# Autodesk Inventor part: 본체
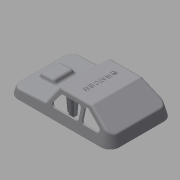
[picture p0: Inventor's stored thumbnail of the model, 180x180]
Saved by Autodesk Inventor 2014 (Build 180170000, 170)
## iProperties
Created: 2015-06
Part Number: 본체
Material: Generic
Document SubType Name: Modeling
Designer: Administrator
Density: 1 g/cm^3
Appearance: Default
Author: Administrator
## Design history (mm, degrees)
sketch "스케치2"
  geometry: L1 (-49, 38)-(49, 38); L2 (61, 26)-(61, -26); L3 (49, -38)-(-49, -38); L4 (-61, -26)-(-61, 26); L5 (-61, 38)-(61, -38); L6 (61, 38)-(-61, -38); A1 r 12 centre (-49, -26) between (-61, -26) and (-49, -38); A2 r 12 centre (-49, 26) between (-49, 38) and (-61, 26); A3 r 12 centre (49, 26) between (61, 26) and (49, 38); A4 r 12 centre (49, -26) between (49, -38) and (61, -26); 1 further point
  constraints: 12 end point, 8 point on circle, 8 point on line, 8 tangent, 4 centre point, 3 equal radius, 2 midpoint, 2 parallel, 1 horizontal, 1 perpendicular
  dimensions: "d0" = 122 distance of L5.end L6.end; "d1" = 76 distance of L6.start L5.end; "d2" = 12 radius of A1
extrude "돌출1" new body sketch "스케치2" distance "d3" = 30; taper "d4" = -15 deg
sketch "스케치3"
  geometry: L1 (-31, 30)-(-61, 30); L2 (-61, 30)-(-61, 10); L3 (-61, 10)-(-31, 30); L4 (49, 30)-(-49, 30) reference; 2 further points
  constraints: 6 end point, 1 collinear, 1 horizontal, 1 perpendicular, 1 vertical alignment
  dimensions: "d5" = 30 distance of L1.start L1.end; "d6" = 20 distance of L1.end L2.end
extrude "돌출2" cut sketch "스케치3" stored distance "d7" = 30; taper "d8" = 0 deg
sketch "스케치4"
  geometry: L1 (1.279, 39.573)-(19, 11.213); L2 (19, 11.213)-(69.975, 8.542); L3 (69.975, 8.542)-(59.484, 45.933); L4 (59.484, 45.933)-(1.279, 39.573); L5 (-49, 0)-(49, 0) reference; L6 (61, 0)-(52.962, 30) reference; 1 further point
  constraints: 8 end point, 1 point on line
  dimensions: "d9" = 3 deg angle of L5 L2; "d10" = 42 horizontal distance of L1.end L6.start; "d11" = 125 deg angle of L1 L2; "d12" = 9 distance from line of L6.start L2
extrude "돌출3" cut sketch "스케치4" stored distance "d13" = 30; taper "d14" = 0 deg
sketch "스케치5"
  geometry: L1 (-31.529, 47.995)-(-11.529, 47.995); L2 (-11.529, 47.995)-(-11.529, 21.995); L3 (-11.529, 21.995)-(-31.529, 21.995); L4 (-31.529, 21.995)-(-31.529, 47.995); L5 (-31.529, 47.995)-(-11.529, 21.995); L6 (-11.529, 47.995)-(-31.529, 21.995); L7 (-30.546, -3.005)-(67.32, -3.005) reference; L8 (-42.529, 60.995)-(-42.529, 8.995) reference; 2 further points
  constraints: 12 end point, 2 midpoint, 2 parallel, 1 horizontal, 1 perpendicular
  dimensions: "d15" = 20 distance of L2.end L3.end; "d16" = 26 distance of L1.end L2.end; "d17" = 38 distance from line of L7 point (-21.529, 34.995); "d18" = 21 distance from line of point (-21.529, 34.995) L8
extrude "돌출4" join sketch "스케치5" distance "d19" = 5; taper "d20" = -20 deg
fillet "모깎기1" dims "d21" = 3
fillet "모깎기2" dims "d22" = 3
fillet "모깎기3" dims "d23" = 3
feature "쉘1" dims "d24" = 2
sketch "스케치6"
  geometry: L1 (-49, 35.929)-(49, 35.929) reference; L2 (58.929, 26)-(58.929, -26) reference; L3 (49, -35.929)-(-49, -35.929) reference; L4 (-58.929, -26)-(-58.929, 26) reference; L5 (49, -38)-(-49, -38) reference; L6 (61, 26)-(61, -26) reference; L7 (-49, 38)-(49, 38) reference; L8 (-61, -26)-(-61, 26) reference; L9 (60, 26)-(60, -26); L10 (49, -37)-(-49, -37); L11 (-60, -26)-(-60, 26); L12 (-49, 37)-(49, 37); A1 r 9.929 centre (-49, 26) between (-49, 35.929) and (-58.929, 26) reference; A2 r 9.929 centre (49, 26) between (58.929, 26) and (49, 35.929) reference; A3 r 9.929 centre (49, -26) between (49, -35.929) and (58.929, -26) reference; A4 r 9.929 centre (-49, -26) between (-58.929, -26) and (-49, -35.929) reference; A5 r 12 centre (49, -26) between (49, -38) and (61, -26) reference; A6 r 12 centre (49, 26) between (61, 26) and (49, 38) reference; A7 r 12 centre (-49, 26) between (-49, 38) and (-61, 26) reference; A8 r 12 centre (-49, -26) between (-61, -26) and (-49, -38) reference; A9 r 11 centre (49, 26) between (60, 26) and (49, 37); A10 r 11 centre (49, -26) between (49, -37) and (60, -26); A11 r 11 centre (-49, -26) between (-60, -26) and (-49, -37); A12 r 11 centre (-49, 26) between (-49, 37) and (-60, 26); 1 further point
  constraints: 8 end point, 8 point on circle, 4 centre point, 7 other
  dimensions: "d25" = 1 distance between parallel lines of L7 L12
extrude "돌출5" join sketch "스케치6" distance "d26" = 1; taper "d27" = 0 deg
sketch "스케치7"
  geometry: L1 (18.172, 12.538)-(8.142, 28.59) reference; L2 (5.598, 30)-(-30.092, 30) reference; L3 (-31.756, 29.496)-(-50.664, 16.891) reference; L4 (10.994, 14.59)-(5.371, 23.59); L5 (2.826, 25)-(-17.138, 25); L6 (8.45, 10)-(-17.138, 10); L7 (-20.138, 22)-(-20.138, 13); L8 (-28.65, 25.557)-(-43.742, 15.496); L9 (-23.986, 23.061)-(-23.986, 13); L10 (-26.986, 10)-(-42.078, 10); A1 r 3 centre (-26.986, 23.061) between (-23.986, 23.061) and (-28.65, 25.557); A2 r 3 centre (-42.078, 13) between (-43.742, 15.496) and (-42.078, 10); A3 r 3 centre (-26.986, 13) between (-26.986, 10) and (-23.986, 13); A4 r 3 centre (-17.138, 22) between (-17.138, 25) and (-20.138, 22); A5 r 3 centre (2.826, 22) between (5.371, 23.59) and (2.826, 25); A6 r 3 centre (8.45, 13) between (8.45, 10) and (10.994, 14.59); A7 r 3 centre (-17.138, 13) between (-20.138, 13) and (-17.138, 10); 5 further points
  constraints: 14 end point, 14 point on circle, 14 tangent, 8 point on line, 7 centre point, 6 equal radius, 5 parallel, 2 perpendicular, 1 collinear
  dimensions: "d34" = 5 distance between parallel lines of L1 L4; "d35" = 5 distance between parallel lines of L2 L5; "d36" = 34 distance from line of L7 point (13.862, 10); "d37" = 15 distance of point (-20.138, 25) point (-20.138, 10); "d38" = 5 distance between parallel lines of L3 L8; "d41" = 28 distance from line of point (-51.986, 10) L9; "d42" = 3 radius of A1
extrude "돌출6" cut sketch "스케치7" stored distance "d43" = 1; taper "d44" = 0 deg
node "작업 평면1"
sketch "스케치8"
  geometry: A1 r 4 centre (-21, 0) between (-17, 0) and (-25, 0); A2 r 4 centre (-10, 0) between (-6, 0) and (-14, 0); A3 r 4 centre (10, 0) between (14, 0) and (6, 0); A4 r 4 centre (21, 0) between (25, 0) and (17, 0); 3 further points
  constraints: 8 point on circle, 4 centre point, 13 other
  dimensions: "d46" = 8 diameter of A1; "d47" = 8 diameter of A2; "d48" = 8 diameter of A3; "d49" = 8 diameter of A4; "d50" = 20 distance of A3.centre A2.centre; "d51" = 10 distance of point (0, 0) A2.centre; "d52" = 11 distance of A2.centre A1.centre; "d53" = 11 distance of A4.centre A3.centre
extrude "돌출7" join sketch "스케치8" stored distance "d54" = 1; taper "d55" = 0 deg
chamfer "모따기1" distance "d56" = 1; stored, may be unused: second distance "d57" = 2, angle "d58" = 45 deg
sketch "스케치9"
  geometry: C1 r 3 at (-40, 0); C2 r 3 at (0, 22); C3 r 3 at (40, 0); C4 r 3 at (0, -22); 1 further point
  constraints: 4 centre point, 2 horizontal alignment, 2 vertical alignment
  dimensions: "d59" = 6 diameter of C1; "d60" = 6 diameter of C2; "d61" = 6 diameter of C3; "d62" = 6 diameter of C4; "d63" = 40 distance of point (0, 0) C1.centre; "d64" = 40 distance of C3.centre point (0, 0); "d65" = 22 distance of C2.centre point (0, 0); "d66" = 44 distance of C2.centre C4.centre
extrude "돌출8" join sketch "스케치9" stored distance "d67" = 1; taper "d68" = 2 deg
sketch "스케치10"
  geometry: 1 further point
node "작업 평면2"
sketch "스케치12"
  geometry: L1 (-5, 23)-(5, 23); L2 (5, 23)-(5, 21); L3 (5, 21)-(-5, 21); L4 (-5, 21)-(-5, 23); L5 (-5, 23)-(5, 21); L6 (5, 23)-(-5, 21); L7 (35, 1)-(45, 1); L8 (45, 1)-(45, -1); L9 (45, -1)-(35, -1); L10 (35, -1)-(35, 1); L11 (35, 1)-(45, -1); L12 (45, 1)-(35, -1); L13 (-45, 1)-(-35, 1); L14 (-35, 1)-(-35, -1); L15 (-35, -1)-(-45, -1); L16 (-45, -1)-(-45, 1); L17 (-45, 1)-(-35, -1); L18 (-35, 1)-(-45, -1); L19 (-5, -21)-(5, -21); L20 (5, -21)-(5, -23); L21 (5, -23)-(-5, -23); L22 (-5, -23)-(-5, -21); L23 (-5, -21)-(5, -23); L24 (5, -21)-(-5, -23); C1 r 3 at (0, 22) reference; C2 r 3 at (-40, 0) reference; C3 r 3 at (0, -22) reference; C4 r 3 at (40, 0) reference; 1 further point
  constraints: 48 end point, 8 midpoint, 8 parallel, 4 horizontal, 4 perpendicular
  dimensions: "d70" = 2 distance of L19.end L20.end; "d71" = 2 distance of L9.end L7.start; "d72" = 2 distance of L1.end L2.end; "d73" = 2 distance of L13.end L14.end; "d74" = 10 horizontal distance of L13.end L15.end; "d75" = 10 distance of L2.end L3.end; "d76" = 10 distance of L19.start L19.end; "d77" = 10 distance of L7.start L7.end
extrude "돌출9" join sketch "스케치12" stored distance "d78" = 1; taper "d79" = 2.5 deg
sketch "스케치13"
  geometry: C1 r 3 at (0, 0) reference; C2 r 3 at (-80, 0) reference; C3 r 3 at (-40, 22) reference; C4 r 3 at (-40, -22) reference; 5 further points
  constraints: 4 coincident
hole "구멍1" sketch "스케치13" at (-80, 0), (-40, 22), (-40, -22), (0, 0) diameter "d80" = 3.242; stored, may be unused: countersink angle "d84" = 90 deg, drill point angle "d86" = 118 deg; dims "d81" = 9, "d82" = 4, "d83" = 2, "d85" = 11
sketch "스케치14"
  geometry: L1 (61, -26)-(61, 26) reference; 2 further points
  constraints: 1 horizontal alignment, 1 other
  dimensions: "d87" = 50 distance from line of L1 point (11, 0)
feature "엠보싱1" sketch "스케치14" dims "d0" = 122, "d1" = 76, "d2" = 12, "d5" = 30, "d6" = 20, "d88" = 0.5, "d89" = 0
fillet "모깎기4" dims "d90" = 3
node "솔리드1"
node "투영된 루프4"
node "투영된 루프5"
node "투영된 루프6"
node "투영된 루프7"
node "투영된 루프8"
node "투영된 루프9"
node "투영된 루프10"
other parameters: "d45" = -63, "d69" = 2
